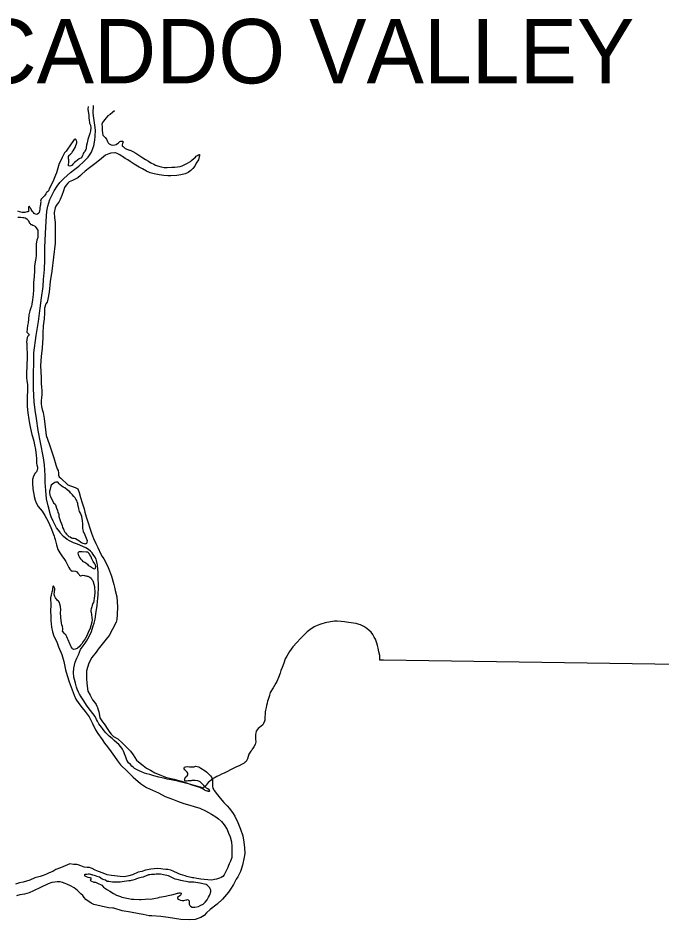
# Model space of a CAD drawing. Extents: x 813775 to 1157140, y 1757555 to 1979907.
# Drawn here: x 865367 to 875936, y 1946127 to 1960929 of the extents above; entities that cross this region are included whole.
import ezdxf

# ---------------------------------------------------------------- set-up
doc = ezdxf.new("R2010")
doc.units = 0
for name, color, linetype in [('Level 2', 7, 'Continuous'), ('Level 6', 7, 'Continuous'), ('Level 9', 7, 'Continuous')]:
    doc.layers.add(name, color=color, linetype=linetype)

msp = doc.modelspace()

# ---------------------------------------------------------------- linework, layer by layer
at = {"layer": 'Level 2'}
for points in [[(866601, 1952123), (866582, 1952151), (866558, 1952179), (866526, 1952205), (866482, 1952232), (866441, 1952250), (866381, 1952276), (866341, 1952295), (866275, 1952317), (866212, 1952347), (866172, 1952372), (866112, 1952422), (866061, 1952480), (866057, 1952490), (865999, 1952565), (865946, 1952673), (865909, 1952741), (865899, 1952774), (865862, 1952922), (865835, 1953036), (865826, 1953174), (865812, 1953306), (865811, 1953419), (865800, 1953597), (865783, 1953713), (865735, 1953965), (865696, 1954162), (865669, 1954356), (865650, 1954494), (865631, 1954632), (865621, 1954843), (865622, 1955093), (865625, 1955273), (865628, 1955437), (865666, 1955719), (865701, 1955951), (865729, 1956165), (865752, 1956339), (865777, 1956525), (865786, 1956637), (865801, 1956801), (865806, 1956959), (865809, 1957165), (865816, 1957393), (865828, 1957597), (865839, 1957757), (865857, 1957841), (865890, 1957951), (865938, 1958051), (865961, 1958091), (866007, 1958168), (866055, 1958230), (866118, 1958298), (866226, 1958393), (866300, 1958451), (866366, 1958498), (866445, 1958574), (866517, 1958648), (866571, 1958725), (866602, 1958805), (866610, 1958831), (866627, 1958927), (866631, 1958991), (866638, 1959091), (866630, 1959169), (866613, 1959284), (866603, 1959370), (866604, 1959495)], [(868668, 1948500), (868630, 1948480), (868602, 1948466), (868572, 1948448), (868536, 1948421), (868510, 1948399), (868490, 1948383), (868470, 1948361), (868454, 1948341), (868440, 1948325), (868420, 1948305), (868408, 1948291), (868364, 1948304), (868316, 1948318), (868260, 1948336), (868204, 1948351), (868137, 1948365), (868071, 1948383), (868031, 1948394), (867975, 1948410), (867935, 1948418), (867880, 1948429), (867816, 1948439), (867778, 1948447), (867676, 1948468), (867594, 1948490), (867531, 1948513), (867483, 1948525), (867443, 1948537), (867393, 1948556), (867357, 1948572), (867310, 1948598), (867278, 1948614), (867260, 1948629), (867236, 1948653), (867212, 1948679), (867183, 1948707), (867155, 1948747), (867137, 1948797), (867126, 1948827), (867098, 1948896), (867080, 1948932), (867055, 1948970), (867021, 1949006), (866987, 1949036), (866943, 1949073), (866912, 1949103), (866862, 1949141), (866808, 1949196), (866781, 1949230), (866753, 1949268), (866737, 1949290), (866694, 1949348), (866670, 1949387), (866656, 1949417), (866631, 1949465), (866597, 1949515), (866557, 1949567), (866504, 1949636), (866435, 1949740), (866405, 1949790), (866375, 1949835), (866358, 1949867), (866340, 1949915), (866326, 1949949), (866311, 1950011), (866295, 1950071), (866285, 1950111), (866280, 1950186), (866282, 1950258), (866307, 1950359), (866333, 1950423), (866359, 1950477), (866394, 1950567), (866438, 1950625), (866468, 1950669), (866489, 1950705), (866515, 1950742), (866549, 1950812), (866571, 1950860), (866600, 1950954), (866616, 1950998), (866633, 1951062), (866649, 1951188), (866664, 1951284), (866672, 1951358), (866677, 1951404), (866681, 1951464), (866686, 1951582), (866686, 1951650), (866683, 1951712), (866681, 1951788), (866681, 1951830), (866678, 1951892), (866674, 1951938), (866670, 1951956), (866666, 1951978), (866653, 1952024), (866647, 1952047), (866625, 1952089), (866601, 1952123)], [(876563, 1950313), (871363, 1950391), (871303, 1950393), (871304, 1950465), (871290, 1950525), (871277, 1950585), (871269, 1950631), (871257, 1950668), (871247, 1950702), (871232, 1950734), (871214, 1950770), (871188, 1950810), (871162, 1950848), (871131, 1950880), (871093, 1950913), (871043, 1950945), (871011, 1950959), (870990, 1950971), (870966, 1950977), (870916, 1950994), (870790, 1951009), (870758, 1951015), (870724, 1951019), (870673, 1951023), (870605, 1951030), (870563, 1951030), (870495, 1951020), (870407, 1951001), (870339, 1950983), (870279, 1950962), (870225, 1950936), (870159, 1950888), (870113, 1950855), (870062, 1950805), (870004, 1950745), (869942, 1950678), (869877, 1950610), (869823, 1950532), (869781, 1950458), (869752, 1950411), (869730, 1950341), (869700, 1950273), (869679, 1950219), (869667, 1950179), (869641, 1950107), (869614, 1950043), (869598, 1950011), (869552, 1949939), (869505, 1949860), (869497, 1949814), (869495, 1949812), (869471, 1949746), (869461, 1949716), (869454, 1949684), (869446, 1949648), (869440, 1949616), (869434, 1949592), (869430, 1949572), (869426, 1949542), (869421, 1949506), (869417, 1949462), (869417, 1949426), (869417, 1949408), (869413, 1949388), (869398, 1949354), (869384, 1949332), (869358, 1949310), (869328, 1949284), (869306, 1949268), (869290, 1949249), (869278, 1949225), (869268, 1949193), (869264, 1949171), (869263, 1949133), (869267, 1949093), (869269, 1949053), (869258, 1949005), (869238, 1948967), (869214, 1948935), (869208, 1948929), (869202, 1948913), (869186, 1948897), (869168, 1948867), (869158, 1948847), (869145, 1948811), (869131, 1948771), (869111, 1948729), (869097, 1948715), (869081, 1948701), (869069, 1948696), (869047, 1948682), (868995, 1948656), (868953, 1948638), (868897, 1948613), (868853, 1948589), (868805, 1948563), (868751, 1948537), (868706, 1948518), (868668, 1948500)]]:
    msp.add_lwpolyline(points, dxfattribs=at)
at = {"layer": 'Level 9'}
for points in [[(866516, 1959476), (866514, 1959432), (866531, 1959328), (866531, 1959284), (866533, 1959256), (866540, 1959202), (866554, 1959168), (866562, 1959126), (866558, 1959080), (866545, 1959034), (866525, 1958970), (866515, 1958934), (866501, 1958882), (866490, 1958840), (866486, 1958802), (866484, 1958784), (866478, 1958770), (866464, 1958746), (866456, 1958734), (866446, 1958720), (866436, 1958704), (866429, 1958686), (866427, 1958674), (866409, 1958634), (866373, 1958619), (866317, 1958577), (866293, 1958557), (866269, 1958533), (866255, 1958517), (866249, 1958511), (866247, 1958507), (866235, 1958501), (866219, 1958497), (866197, 1958502), (866195, 1958508), (866193, 1958520), (866197, 1958532), (866199, 1958552), (866199, 1958562), (866199, 1958602), (866197, 1958618), (866196, 1958632), (866198, 1958654)], [(866951, 1959408), (866919, 1959378), (866877, 1959346), (866843, 1959322), (866811, 1959292), (866794, 1959264), (866768, 1959239), (866754, 1959215), (866742, 1959185), (866746, 1959141), (866747, 1959089), (866751, 1959037), (866757, 1959008), (866795, 1958970), (866818, 1958940), (866836, 1958904), (866848, 1958882), (866864, 1958864), (866898, 1958849), (866921, 1958841), (866955, 1958847), (866977, 1958855), (866999, 1958869), (867014, 1958879), (867030, 1958897), (867040, 1958903), (867054, 1958907), (867064, 1958909), (867080, 1958908), (867093, 1958896), (867089, 1958882), (867083, 1958868), (867077, 1958846), (867077, 1958836), (867079, 1958830), (867091, 1958818), (867123, 1958786), (867194, 1958762), (867206, 1958758), (867250, 1958739), (867298, 1958711), (867348, 1958681), (867417, 1958632), (867461, 1958606), (867509, 1958578), (867548, 1958555), (867594, 1958529), (867626, 1958517), (867658, 1958505), (867718, 1958486), (867767, 1958476), (867813, 1958476), (867891, 1958479), (867943, 1958483), (867987, 1958487), (868029, 1958492), (868063, 1958504), (868105, 1958524), (868135, 1958540), (868197, 1958577), (868217, 1958593), (868259, 1958627), (868282, 1958645), (868292, 1958661), (868302, 1958669), (868312, 1958673), (868318, 1958677), (868324, 1958681), (868332, 1958683), (868340, 1958687)], [(866198, 1958654), (866206, 1958674), (866214, 1958686), (866228, 1958697), (866232, 1958699), (866250, 1958719), (866256, 1958725), (866272, 1958749), (866304, 1958805), (866317, 1958837), (866327, 1958863), (866331, 1958881), (866333, 1958901), (866325, 1958915), (866323, 1958923), (866321, 1958931), (866315, 1958937), (866311, 1958941), (866303, 1958939), (866289, 1958933), (866267, 1958903), (866241, 1958866), (866219, 1958834), (866178, 1958776), (866158, 1958746), (866130, 1958714), (866116, 1958686), (866094, 1958640), (866065, 1958582), (866045, 1958540), (866021, 1958467), (865996, 1958391), (865982, 1958349), (865962, 1958293), (865938, 1958241), (865909, 1958189), (865879, 1958121), (865873, 1958107), (865865, 1958095), (865851, 1958079), (865835, 1958063), (865823, 1958046), (865814, 1958026), (865804, 1958010), (865794, 1958004), (865772, 1957982), (865750, 1957964), (865746, 1957958), (865742, 1957942), (865738, 1957926), (865740, 1957910), (865738, 1957886), (865734, 1957866), (865729, 1957846), (865727, 1957816), (865727, 1957788), (865719, 1957766), (865713, 1957736), (865707, 1957724), (865685, 1957708), (865683, 1957708), (865669, 1957702), (865643, 1957714), (865633, 1957722), (865619, 1957739), (865611, 1957749), (865605, 1957755), (865595, 1957771), (865583, 1957789), (865575, 1957803), (865568, 1957815), (865560, 1957827), (865554, 1957835), (865550, 1957837), (865546, 1957841), (865544, 1957833), (865540, 1957823), (865538, 1957799), (865541, 1957783), (865543, 1957769), (865541, 1957759), (865539, 1957755), (865527, 1957749), (865519, 1957749), (865497, 1957745), (865477, 1957739), (865467, 1957737), (865437, 1957738), (865411, 1957742), (865392, 1957748), (865362, 1957760)], [(868340, 1958687), (868346, 1958687), (868348, 1958681), (868348, 1958667), (868341, 1958653), (868327, 1958603), (868293, 1958547), (868267, 1958499), (868234, 1958461), (868206, 1958425), (868162, 1958395), (868108, 1958374), (868038, 1958358), (867972, 1958345), (867874, 1958341), (867825, 1958340), (867761, 1958344), (867683, 1958356), (867599, 1958373), (867537, 1958391), (867478, 1958416), (867408, 1958456), (867354, 1958484), (867273, 1958531), (867209, 1958573), (867169, 1958600), (867128, 1958626), (867082, 1958654), (867058, 1958668), (867038, 1958683), (866992, 1958705), (866969, 1958715), (866957, 1958715), (866891, 1958713), (866859, 1958702), (866803, 1958678), (866738, 1958622), (866648, 1958553), (866538, 1958469), (866470, 1958416), (866417, 1958366), (866391, 1958344), (866347, 1958308), (866303, 1958283), (866263, 1958265), (866209, 1958239), (866183, 1958219), (866157, 1958188), (866131, 1958146), (866116, 1958092), (866088, 1958014), (866061, 1957950), (866035, 1957906), (866011, 1957874), (865987, 1957840), (865975, 1957814), (865960, 1957738), (865964, 1957650), (865975, 1957572), (865978, 1957430), (865975, 1957232), (865952, 1957006), (865922, 1956776), (865897, 1956606), (865876, 1956432), (865857, 1956314), (865845, 1956268), (865821, 1956238), (865799, 1956170), (865802, 1956090), (865794, 1955990), (865781, 1955876), (865772, 1955758), (865774, 1955676), (865771, 1955606), (865763, 1955510), (865748, 1955372), (865735, 1955228), (865748, 1955026), (865745, 1954928), (865751, 1954876), (865758, 1954810), (865760, 1954752), (865755, 1954700), (865749, 1954646), (865749, 1954600), (865753, 1954554), (865766, 1954503), (865782, 1954457), (865797, 1954355), (865831, 1954079), (865880, 1953940), (865923, 1953808), (865953, 1953714), (865988, 1953598), (866010, 1953531), (866025, 1953503), (866029, 1953461), (866031, 1953425), (866045, 1953401), (866068, 1953375)], [(865363, 1957660), (865407, 1957660), (865445, 1957656), (865465, 1957655), (865483, 1957651), (865513, 1957635), (865528, 1957619), (865538, 1957597), (865548, 1957577), (865558, 1957563), (865564, 1957557), (865574, 1957547), (865578, 1957543), (865592, 1957539), (865612, 1957530), (865636, 1957518), (865651, 1957506), (865667, 1957486), (865677, 1957472), (865693, 1957446), (865693, 1957432), (865690, 1957364), (865690, 1957328), (865674, 1957286), (865664, 1957222), (865663, 1957164), (865664, 1957040), (865658, 1956984), (865648, 1956930), (865635, 1956856), (865635, 1956778), (865630, 1956686), (865620, 1956586), (865621, 1956468), (865614, 1956392), (865604, 1956302), (865593, 1956232), (865587, 1956198), (865571, 1956158), (865559, 1956126), (865546, 1956060), (865540, 1955986), (865532, 1955926), (865525, 1955884), (865509, 1955776), (865527, 1955756), (865541, 1955746), (865548, 1955734), (865538, 1955716), (865530, 1955706), (865518, 1955688), (865508, 1955612), (865510, 1955582), (865511, 1955502), (865515, 1955436), (865516, 1955338), (865511, 1955254), (865509, 1955190), (865507, 1955129), (865508, 1955029), (865514, 1954973), (865521, 1954913), (865525, 1954865), (865521, 1954799), (865516, 1954729), (865518, 1954641), (865519, 1954555), (865526, 1954449), (865546, 1954341), (865555, 1954275), (865573, 1954190), (865594, 1954096), (865604, 1954064), (865627, 1953984), (865639, 1953922), (865652, 1953846), (865666, 1953754), (865669, 1953698), (865671, 1953654)], [(865671, 1953654), (865673, 1953621), (865677, 1953595), (865684, 1953559), (865686, 1953537), (865680, 1953511), (865676, 1953499), (865670, 1953481), (865650, 1953458), (865622, 1953410), (865607, 1953354), (865605, 1953288), (865612, 1953206), (865616, 1953170), (865628, 1953115), (865633, 1953075), (865651, 1953019), (865667, 1952971), (865700, 1952915), (865762, 1952834), (865809, 1952764), (865862, 1952666), (865908, 1952569), (865959, 1952427), (865968, 1952403), (865976, 1952371), (865986, 1952327), (865996, 1952285), (866007, 1952247), (866021, 1952208), (866053, 1952152), (866086, 1952104), (866128, 1952044), (866150, 1952008), (866163, 1951987), (866181, 1951955), (866199, 1951911), (866217, 1951883), (866235, 1951867), (866254, 1951853), (866282, 1951857), (866312, 1951854), (866332, 1951840), (866350, 1951820), (866368, 1951798), (866378, 1951788), (866392, 1951776), (866414, 1951778), (866428, 1951784), (866458, 1951781), (866475, 1951777), (866483, 1951775), (866501, 1951771), (866515, 1951767), (866537, 1951759), (866547, 1951753), (866565, 1951735), (866575, 1951719), (866587, 1951701), (866599, 1951679), (866624, 1951598), (866629, 1951492), (866617, 1951410), (866613, 1951364), (866604, 1951336), (866592, 1951314), (866584, 1951286), (866576, 1951264), (866566, 1951234), (866562, 1951212), (866562, 1951190), (866565, 1951172), (866571, 1951138), (866581, 1951086), (866585, 1951060), (866580, 1951016), (866550, 1950916), (866519, 1950844), (866499, 1950789), (866471, 1950741), (866437, 1950695), (866413, 1950661), (866392, 1950637), (866368, 1950611), (866350, 1950593), (866336, 1950581), (866306, 1950574), (866278, 1950568), (866262, 1950578), (866256, 1950586), (866239, 1950610), (866235, 1950620), (866205, 1950684), (866199, 1950696), (866189, 1950722), (866180, 1950748), (866166, 1950775), (866154, 1950805), (866138, 1950819), (866130, 1950827), (866098, 1950867)], [(866068, 1953375), (866184, 1953270), (866287, 1953231), (866305, 1953227), (866347, 1953201), (866370, 1953145), (866394, 1953059), (866419, 1952971), (866453, 1952874), (866464, 1952822), (866486, 1952744), (866519, 1952642), (866546, 1952555), (866574, 1952477), (866605, 1952387), (866643, 1952303), (866676, 1952240), (866725, 1952132), (866747, 1952090), (866777, 1952052), (866808, 1951993), (866844, 1951913), (866867, 1951855), (866903, 1951771), (866940, 1951630), (866949, 1951590), (866963, 1951534), (866988, 1951430), (866999, 1951266), (866996, 1951142), (866988, 1951060), (866976, 1951012), (866919, 1950900), (866863, 1950798), (866816, 1950733), (866748, 1950655), (866685, 1950569), (866647, 1950523), (866579, 1950434), (866528, 1950340), (866490, 1950216), (866491, 1950098), (866494, 1950006), (866511, 1949884), (866549, 1949818), (866590, 1949739), (866622, 1949699), (866650, 1949665), (866662, 1949635), (866669, 1949613), (866683, 1949575), (866693, 1949543), (866699, 1949513), (866708, 1949446), (866754, 1949380), (866781, 1949346), (866839, 1949255), (866872, 1949205), (866894, 1949177), (866936, 1949139), (867007, 1949098), (867077, 1949034), (867123, 1948986), (867214, 1948895), (867255, 1948837), (867311, 1948752), (867344, 1948720), (867420, 1948662), (867476, 1948621), (867543, 1948583), (867613, 1948544), (867686, 1948514), (867790, 1948473), (867880, 1948449), (867931, 1948438), (868007, 1948416), (868053, 1948406), (868095, 1948391), (868151, 1948371), (868202, 1948351), (868292, 1948324), (868346, 1948306), (868370, 1948298), (868388, 1948291), (868404, 1948281), (868421, 1948267), (868433, 1948259), (868447, 1948251), (868467, 1948247), (868477, 1948245), (868489, 1948243), (868499, 1948243), (868509, 1948243), (868513, 1948245), (868515, 1948247), (868517, 1948249), (868503, 1948265), (868485, 1948279), (868463, 1948289), (868452, 1948299), (868430, 1948319)], [(866412, 1952750), (866394, 1952801), (866376, 1952833), (866363, 1952873), (866357, 1952915), (866355, 1952915), (866347, 1952961), (866339, 1952989), (866332, 1953011), (866318, 1953031), (866304, 1953057), (866282, 1953079), (866262, 1953106), (866246, 1953120), (866227, 1953136), (866215, 1953152), (866175, 1953188), (866135, 1953218), (866107, 1953231), (866084, 1953247), (866056, 1953269), (866050, 1953277), (866042, 1953287), (866018, 1953311), (866004, 1953313), (865986, 1953311), (865972, 1953307), (865956, 1953296), (865910, 1953260), (865908, 1953246), (865892, 1953198), (865883, 1953164), (865883, 1953140), (865891, 1953100), (865899, 1953074), (865919, 1953038), (865936, 1952999), (865952, 1952973), (865978, 1952951), (865988, 1952921), (865999, 1952887), (866013, 1952847), (866021, 1952815), (866029, 1952799), (866035, 1952779), (866039, 1952751)], [(866039, 1952751), (866062, 1952664), (866078, 1952630), (866089, 1952600), (866099, 1952570), (866113, 1952540), (866121, 1952524), (866135, 1952494), (866151, 1952474), (866160, 1952458), (866166, 1952452), (866202, 1952423), (866224, 1952413), (866244, 1952399), (866262, 1952391), (866268, 1952393), (866288, 1952391), (866310, 1952385), (866365, 1952352), (866395, 1952334), (866407, 1952324), (866433, 1952312), (866453, 1952304), (866469, 1952302), (866481, 1952306), (866487, 1952306), (866495, 1952312), (866503, 1952324), (866505, 1952352), (866497, 1952372), (866493, 1952388), (866480, 1952416), (866468, 1952442), (866450, 1952482), (866444, 1952494), (866442, 1952508), (866432, 1952552), (866433, 1952556), (866431, 1952582), (866431, 1952630), (866423, 1952684), (866420, 1952712), (866412, 1952750)], [(866422, 1952166), (866400, 1952168), (866384, 1952168), (866368, 1952168), (866360, 1952164), (866352, 1952156), (866350, 1952146), (866356, 1952126), (866358, 1952114), (866364, 1952098), (866376, 1952076), (866393, 1952056), (866413, 1952030), (866433, 1952012), (866461, 1952000), (866481, 1951987)], [(866481, 1951987), (866505, 1951965), (866517, 1951951), (866532, 1951939), (866554, 1951929), (866574, 1951917), (866586, 1951907), (866594, 1951903), (866608, 1951893), (866626, 1951891), (866628, 1951891), (866638, 1951900), (866644, 1951928), (866636, 1951951), (866628, 1951973), (866603, 1952011), (866581, 1952053), (866575, 1952069), (866561, 1952095), (866548, 1952117), (866538, 1952127), (866532, 1952139), (866518, 1952155), (866512, 1952163), (866500, 1952163), (866492, 1952164), (866422, 1952166)], [(866098, 1950867), (866105, 1950889), (866105, 1950909), (866095, 1950945), (866087, 1950971), (866079, 1951003), (866070, 1951087), (866066, 1951179), (866069, 1951211), (866063, 1951272), (866053, 1951312), (866046, 1951336), (866032, 1951358), (866016, 1951372), (866002, 1951388), (865994, 1951398), (865982, 1951414), (865970, 1951436), (865964, 1951454), (865961, 1951470), (865965, 1951512), (865971, 1951548), (865971, 1951552), (865969, 1951562), (865965, 1951576), (865959, 1951590), (865957, 1951598), (865949, 1951604), (865943, 1951604), (865939, 1951599), (865935, 1951559), (865931, 1951539), (865921, 1951507), (865909, 1951465), (865902, 1951413), (865904, 1951291), (865901, 1951200), (865904, 1951110), (865906, 1951044), (865919, 1950930), (865935, 1950854), (865954, 1950786), (866002, 1950694), (866033, 1950611), (866088, 1950483), (866117, 1950371), (866148, 1950234), (866174, 1950138), (866209, 1950036), (866287, 1949817), (866315, 1949753), (866366, 1949679), (866418, 1949610), (866471, 1949546), (866533, 1949459), (866590, 1949349), (866641, 1949249), (866677, 1949186), (866748, 1949090), (866787, 1949030), (866837, 1948969), (866894, 1948885), (866950, 1948809), (867001, 1948738), (867047, 1948674), (867156, 1948567), (867259, 1948472), (867378, 1948368), (867475, 1948299), (867671, 1948212), (867780, 1948153), (867901, 1948110), (867985, 1948076), (868087, 1948039), (868188, 1948012), (868260, 1947990), (868352, 1947961), (868443, 1947919), (868543, 1947862), (868614, 1947818), (868658, 1947785), (868704, 1947745), (868749, 1947687), (868797, 1947612), (868824, 1947554), (868848, 1947494), (868869, 1947410), (868877, 1947334), (868878, 1947264), (868878, 1947198), (868875, 1947150), (868855, 1947094), (868831, 1947050), (868821, 1947020), (868811, 1946988), (868772, 1946910), (868754, 1946878), (868750, 1946870), (868728, 1946842), (868700, 1946825), (868676, 1946815)], [(868430, 1948319), (868418, 1948333), (868400, 1948353), (868378, 1948370), (868354, 1948392), (868317, 1948408), (868277, 1948416), (868263, 1948418), (868219, 1948417), (868207, 1948413), (868179, 1948411), (868157, 1948411), (868137, 1948403), (868125, 1948405), (868113, 1948407), (868107, 1948413), (868103, 1948425), (868101, 1948437), (868107, 1948449), (868119, 1948473), (868129, 1948483), (868143, 1948495), (868153, 1948511), (868156, 1948525), (868154, 1948539), (868142, 1948553), (868122, 1948575), (868106, 1948591), (868094, 1948607), (868092, 1948613), (868092, 1948625), (868098, 1948637), (868114, 1948639), (868146, 1948643), (868180, 1948639), (868258, 1948642), (868282, 1948652), (868308, 1948648), (868332, 1948638), (868366, 1948618), (868437, 1948577), (868465, 1948553), (868495, 1948525), (868527, 1948491), (868542, 1948471), (868558, 1948432), (868560, 1948418), (868560, 1948374), (868558, 1948348), (868559, 1948318), (868563, 1948290), (868579, 1948262), (868587, 1948252), (868640, 1948182), (868686, 1948127), (868745, 1948053), (868797, 1947999), (868839, 1947954), (868898, 1947872), (868924, 1947830), (868975, 1947729), (869020, 1947615), (869055, 1947509), (869073, 1947403), (869082, 1947311), (869091, 1947216), (869081, 1947156), (869054, 1947027), (869018, 1946921), (868973, 1946837), (868947, 1946795), (868905, 1946709), (868854, 1946633), (868822, 1946586), (868721, 1946466), (868633, 1946385), (868523, 1946301), (868459, 1946242), (868420, 1946200), (868366, 1946166), (868274, 1946135), (868176, 1946127), (868041, 1946134), (867935, 1946151), (867829, 1946165), (867710, 1946184), (867562, 1946193), (867522, 1946197), (867422, 1946216), (867353, 1946230), (867215, 1946253), (867079, 1946278), (866942, 1946321), (866922, 1946323), (866850, 1946329), (866729, 1946354), (866613, 1946383), (866569, 1946401), (866482, 1946462), (866454, 1946496), (866430, 1946526)], [(868676, 1946815), (868658, 1946809), (868626, 1946797), (868590, 1946789), (868546, 1946781), (868482, 1946786), (868422, 1946792), (868368, 1946799), (868300, 1946809), (868253, 1946817), (868229, 1946819), (868161, 1946834), (868139, 1946840), (868113, 1946850), (868071, 1946860), (868033, 1946873), (867996, 1946891), (867982, 1946897), (867924, 1946925), (867876, 1946944), (867828, 1946954), (867794, 1946956), (867746, 1946962), (867709, 1946967), (867663, 1946971), (867599, 1946969), (867549, 1946960), (867491, 1946948), (867461, 1946942), (867401, 1946925), (867341, 1946909), (867245, 1946867), (867185, 1946850), (867115, 1946834), (867043, 1946839), (866899, 1946856), (866828, 1946868), (866762, 1946894), (866688, 1946923), (866633, 1946947), (866585, 1946970), (866569, 1946978), (866541, 1946988), (866521, 1946988), (866501, 1946986), (866451, 1946992), (866399, 1947013), (866354, 1947031), (866330, 1947037), (866278, 1947037), (866220, 1947046), (866066, 1946985), (865990, 1946953), (865936, 1946925), (865880, 1946898), (865832, 1946878), (865808, 1946868), (865782, 1946856), (865728, 1946843), (865644, 1946817), (865560, 1946778), (865454, 1946748), (865392, 1946735), (865326, 1946717)], [(867756, 1946870), (867706, 1946877), (867672, 1946879), (867634, 1946879), (867608, 1946875), (867596, 1946873), (867560, 1946874), (867528, 1946870), (867508, 1946866), (867486, 1946858), (867442, 1946842), (867420, 1946832), (867390, 1946825), (867346, 1946813), (867312, 1946801), (867288, 1946793), (867254, 1946781), (867222, 1946776), (867206, 1946772), (867188, 1946770), (867148, 1946766), (867110, 1946758), (867078, 1946752), (867046, 1946747), (867022, 1946745), (866993, 1946747), (866941, 1946749), (866917, 1946747), (866883, 1946752), (866855, 1946756), (866829, 1946758), (866801, 1946778), (866779, 1946784), (866749, 1946796), (866727, 1946811), (866702, 1946827), (866664, 1946841), (866640, 1946853), (866616, 1946857), (866588, 1946865), (866588, 1946867), (866578, 1946869), (866564, 1946874), (866540, 1946878), (866540, 1946880), (866518, 1946878), (866498, 1946876), (866474, 1946874), (866466, 1946872), (866458, 1946870), (866458, 1946858), (866466, 1946850), (866486, 1946842), (866512, 1946828), (866548, 1946824), (866560, 1946816), (866562, 1946808), (866560, 1946790), (866552, 1946782), (866552, 1946780), (866564, 1946768), (866609, 1946749), (866637, 1946745), (866661, 1946737), (866673, 1946733), (866743, 1946696), (866768, 1946668), (866804, 1946642), (866836, 1946624), (866874, 1946598), (866932, 1946561), (866983, 1946535), (867047, 1946510), (867073, 1946502), (867127, 1946488), (867180, 1946478), (867228, 1946471), (867268, 1946469), (867360, 1946464), (867388, 1946464), (867452, 1946470), (867484, 1946472), (867540, 1946471), (867570, 1946473), (867596, 1946477), (867658, 1946489), (867682, 1946497), (867684, 1946501), (867724, 1946508), (867790, 1946518), (867830, 1946526), (867885, 1946537), (867889, 1946539), (867913, 1946543), (867967, 1946561), (867984, 1946569), (867995, 1946565), (868013, 1946571), (868031, 1946572), (868043, 1946568), (868047, 1946560)], [(868350, 1946729), (868254, 1946747), (868224, 1946745), (868194, 1946748), (868170, 1946750), (868128, 1946758), (868089, 1946766), (868069, 1946770), (868037, 1946777), (868001, 1946787), (867945, 1946799), (867859, 1946842), (867838, 1946850), (867756, 1946870)], [(866430, 1946526), (866397, 1946556), (866341, 1946609), (866287, 1946655), (866226, 1946688), (866168, 1946716), (866142, 1946728), (866096, 1946742), (866060, 1946751), (866012, 1946751), (865969, 1946749), (865923, 1946741), (865861, 1946720), (865734, 1946662), (865620, 1946603), (865548, 1946572), (865474, 1946550), (865398, 1946538), (865344, 1946523)], [(868047, 1946560), (868041, 1946542), (868023, 1946524), (868005, 1946511), (867987, 1946495), (867985, 1946495), (867987, 1946481), (867999, 1946471), (868009, 1946465), (868033, 1946454), (868061, 1946446), (868091, 1946446), (868125, 1946460), (868139, 1946460), (868148, 1946462), (868160, 1946460), (868172, 1946449), (868176, 1946443), (868178, 1946429), (868176, 1946411), (868176, 1946403), (868176, 1946387), (868186, 1946367), (868200, 1946353), (868226, 1946339), (868271, 1946335), (868327, 1946348), (868367, 1946368), (868404, 1946388), (868440, 1946422), (868470, 1946458), (868496, 1946504), (868508, 1946530), (868520, 1946557), (868524, 1946567), (868529, 1946597), (868529, 1946615), (868521, 1946636), (868517, 1946654), (868495, 1946678), (868473, 1946698), (868457, 1946708), (868428, 1946714), (868400, 1946720), (868380, 1946724), (868356, 1946729), (868350, 1946729)]]:
    msp.add_lwpolyline(points, dxfattribs=at)

# ---------------------------------------------------------------- texts
at = {"layer": 'Level 6'}
msp.add_text('CADDO VALLEY', height=1056, dxfattribs=at).set_placement((864653, 1959857))

doc.saveas('drawing.dxf')
